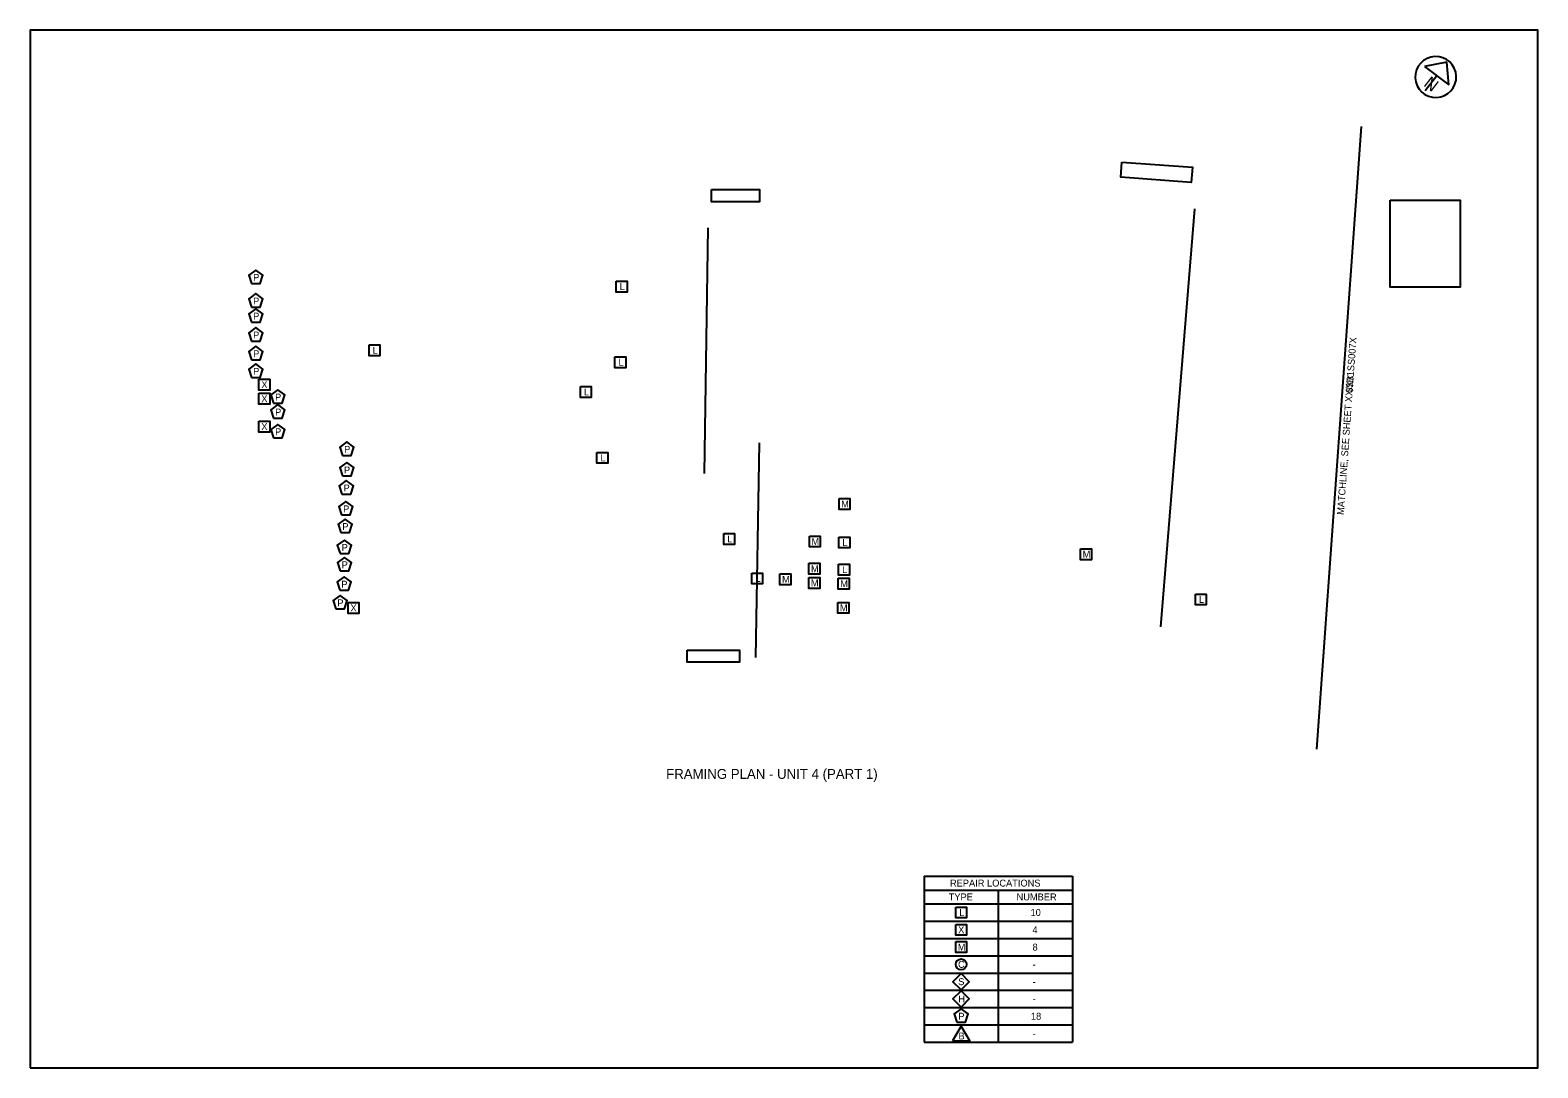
# Model space of a CAD drawing. Extents: x 100 to 130.5, y 100 to 121.
import ezdxf

# ---------------------------------------------------------------- set-up
doc = ezdxf.new("R2010")
doc.units = 0
for name, color, linetype in [('BR_P_Gen_Text', 7, 'Continuous'), ('BR_X_Sub_Centerline', 7, 'Continuous'), ('BR_X_Sub_Text', 7, 'Continuous'), ('SC_Scratch1', 7, 'Continuous'), ('SH_Data', 7, 'Continuous'), ('SH_Masking', 7, 'Continuous')]:
    doc.layers.add(name, color=color, linetype=linetype)

msp = doc.modelspace()

# ---------------------------------------------------------------- linework, layer by layer
at = {"layer": 'BR_P_Gen_Text'}
for p, q in [((126.929, 119.052), (126.022, 106.448)), ((118.083, 103.879), (118.083, 100.519)), ((118.083, 103.879), (121.083, 103.879)), ((121.083, 103.879), (121.083, 100.519)), ((118.083, 103.599), (121.083, 103.599)), ((119.583, 103.599), (119.583, 100.519)), ((118.083, 103.319), (121.083, 103.319)), ((118.083, 102.969), (121.083, 102.969)), ((118.083, 102.619), (121.083, 102.619)), ((118.083, 102.269), (121.083, 102.269)), ((118.083, 101.919), (121.083, 101.919)), ((118.083, 101.569), (121.083, 101.569)), ((118.083, 101.219), (121.083, 101.219)), ((118.083, 100.869), (121.083, 100.869)), ((118.083, 100.519), (121.083, 100.519))]:
    msp.add_line(p, q, dxfattribs=at)
for points in [[(104.479, 115.875), (104.655, 115.875), (104.71, 116.042), (104.567, 116.146), (104.425, 116.042)], [(111.854, 115.92), (112.074, 115.92), (112.074, 115.7), (111.854, 115.7)], [(104.479, 115.396), (104.655, 115.396), (104.71, 115.564), (104.567, 115.668), (104.425, 115.564)], [(104.479, 115.091), (104.655, 115.091), (104.71, 115.259), (104.567, 115.362), (104.425, 115.259)], [(104.479, 114.708), (104.655, 114.708), (104.71, 114.876), (104.567, 114.98), (104.425, 114.876)], [(104.479, 114.33), (104.655, 114.33), (104.71, 114.498), (104.567, 114.602), (104.425, 114.498)], [(106.856, 114.63), (107.076, 114.63), (107.076, 114.41), (106.856, 114.41)], [(111.829, 114.389), (112.049, 114.389), (112.049, 114.169), (111.829, 114.169)], [(104.479, 113.973), (104.655, 113.973), (104.71, 114.141), (104.567, 114.245), (104.425, 114.141)], [(104.627, 113.936), (104.847, 113.936), (104.847, 113.716), (104.627, 113.716)], [(111.13, 113.787), (111.35, 113.787), (111.35, 113.567), (111.13, 113.567)], [(104.627, 113.651), (104.847, 113.651), (104.847, 113.431), (104.627, 113.431)], [(104.923, 113.453), (105.099, 113.453), (105.154, 113.621), (105.011, 113.724), (104.868, 113.621)], [(104.923, 113.15), (105.099, 113.15), (105.154, 113.317), (105.011, 113.421), (104.868, 113.317)], [(104.627, 113.087), (104.847, 113.087), (104.847, 112.867), (104.627, 112.867)], [(104.923, 112.751), (105.099, 112.751), (105.154, 112.918), (105.011, 113.022), (104.868, 112.918)], [(106.319, 112.395), (106.496, 112.395), (106.55, 112.563), (106.407, 112.666), (106.265, 112.563)], [(106.316, 111.978), (106.493, 111.978), (106.547, 112.146), (106.404, 112.249), (106.262, 112.146)], [(111.466, 112.455), (111.686, 112.455), (111.686, 112.235), (111.466, 112.235)], [(106.308, 111.613), (106.484, 111.613), (106.538, 111.781), (106.396, 111.885), (106.253, 111.781)], [(106.299, 111.19), (106.475, 111.19), (106.53, 111.358), (106.387, 111.462), (106.244, 111.358)], [(116.365, 111.52), (116.585, 111.52), (116.585, 111.3), (116.365, 111.3)], [(106.283, 110.832), (106.459, 110.832), (106.514, 111), (106.371, 111.103), (106.229, 111)], [(114.031, 110.813), (114.251, 110.813), (114.251, 110.593), (114.031, 110.593)], [(115.764, 110.762), (115.984, 110.762), (115.984, 110.542), (115.764, 110.542)], [(116.359, 110.742), (116.579, 110.742), (116.579, 110.522), (116.359, 110.522)], [(106.269, 110.409), (106.445, 110.409), (106.499, 110.577), (106.357, 110.68), (106.214, 110.577)], [(121.251, 110.503), (121.471, 110.503), (121.471, 110.283), (121.251, 110.283)], [(106.271, 110.059), (106.448, 110.059), (106.502, 110.227), (106.36, 110.33), (106.217, 110.227)], [(115.754, 110.211), (115.974, 110.211), (115.974, 109.991), (115.754, 109.991)], [(116.353, 110.192), (116.573, 110.192), (116.573, 109.972), (116.353, 109.972)], [(106.263, 109.665), (106.439, 109.665), (106.494, 109.833), (106.351, 109.937), (106.208, 109.833)], [(114.598, 110.014), (114.818, 110.014), (114.818, 109.794), (114.598, 109.794)], [(115.169, 109.996), (115.389, 109.996), (115.389, 109.776), (115.169, 109.776)], [(115.752, 109.924), (115.972, 109.924), (115.972, 109.704), (115.752, 109.704)], [(116.347, 109.908), (116.567, 109.908), (116.567, 109.688), (116.347, 109.688)], [(106.181, 109.289), (106.357, 109.289), (106.412, 109.457), (106.269, 109.56), (106.127, 109.457)], [(123.572, 109.589), (123.792, 109.589), (123.792, 109.369), (123.572, 109.369)], [(106.43, 109.418), (106.65, 109.418), (106.65, 109.198), (106.43, 109.198)], [(116.34, 109.42), (116.56, 109.42), (116.56, 109.2), (116.34, 109.2)], [(118.723, 103.254), (118.943, 103.254), (118.943, 103.034), (118.723, 103.034)], [(118.723, 102.904), (118.943, 102.904), (118.943, 102.684), (118.723, 102.684)], [(118.723, 102.554), (118.943, 102.554), (118.943, 102.334), (118.723, 102.334)], [(118.833, 101.909), (118.998, 101.744), (118.833, 101.579), (118.668, 101.744)], [(118.833, 101.559), (118.998, 101.394), (118.833, 101.229), (118.668, 101.394)], [(118.745, 100.923), (118.922, 100.923), (118.976, 101.091), (118.833, 101.194), (118.691, 101.091)], [(118.66, 100.544), (119.007, 100.544), (118.833, 100.844)]]:
    msp.add_lwpolyline(points, close=True, dxfattribs=at)
msp.add_circle((118.833, 102.094), 0.11, dxfattribs=at)
at = {"layer": 'BR_X_Sub_Centerline'}
for p, q in [((123.554, 117.383), (122.869, 108.926)), ((113.711, 116.998), (113.638, 112.031)), ((114.681, 108.303), (114.755, 112.646))]:
    msp.add_line(p, q, dxfattribs=at)
at = {"layer": 'BR_X_Sub_Text'}
for points in [[(122.087, 118.331), (123.511, 118.226), (123.488, 117.92), (122.065, 118.025)], [(113.781, 117.773), (114.754, 117.773), (114.754, 117.528), (113.781, 117.528)], [(113.291, 108.45), (114.352, 108.45), (114.352, 108.209), (113.291, 108.209)]]:
    msp.add_lwpolyline(points, close=True, dxfattribs=at)
at = {"layer": 'SC_Scratch1'}
msp.add_lwpolyline([(100, 100), (130.5, 100), (130.5, 121), (100, 121)], close=True, dxfattribs=at)
at = {"layer": 'SH_Data'}
for p, q in [((128.662, 120.349), (128.21, 120.265)), ((128.21, 120.265), (128.699, 119.891)), ((128.699, 119.891), (128.662, 120.349)), ((128.454, 120.078), (128.219, 119.771))]:
    msp.add_line(p, q, dxfattribs=at)
msp.add_arc((128.435, 120.052), 0.415, 92.3383, 92.3218, dxfattribs=at)
at = {"layer": 'SH_Masking'}
msp.add_lwpolyline([(127.511, 117.56), (128.927, 117.56), (128.927, 115.801), (127.511, 115.801)], close=True, dxfattribs=at)

# ---------------------------------------------------------------- texts
at = {"layer": 'BR_P_Gen_Text'}
for s, height, p in [('P', 0.14, (104.511, 115.926)), ('L', 0.14, (111.926, 115.74)), ('P', 0.14, (104.511, 115.448)), ('P', 0.14, (104.511, 115.142)), ('P', 0.14, (104.511, 114.76)), ('P', 0.14, (104.511, 114.382)), ('L', 0.14, (106.928, 114.45)), ('P', 0.14, (104.511, 114.025)), ('L', 0.14, (111.901, 114.209)), ('X', 0.14, (104.677, 113.756)), ('X', 0.14, (104.677, 113.471)), ('P', 0.14, (104.955, 113.504)), ('L', 0.14, (111.202, 113.607)), ('P', 0.14, (104.955, 113.201)), ('X', 0.14, (104.677, 112.907)), ('P', 0.14, (104.955, 112.802)), ('P', 0.14, (106.351, 112.446)), ('L', 0.14, (111.538, 112.275)), ('P', 0.14, (106.348, 112.029)), ('P', 0.14, (106.34, 111.665)), ('P', 0.14, (106.331, 111.242)), ('M', 0.14, (116.407, 111.34)), ('P', 0.14, (106.315, 110.883)), ('L', 0.14, (114.103, 110.633)), ('M', 0.14, (115.805, 110.582)), ('P', 0.14, (106.301, 110.46)), ('L', 0.14, (116.431, 110.562)), ('M', 0.14, (121.292, 110.323)), ('P', 0.14, (106.303, 110.11)), ('M', 0.14, (115.796, 110.031)), ('L', 0.14, (116.425, 110.012)), ('P', 0.14, (106.295, 109.717)), ('L', 0.14, (114.67, 109.834)), ('M', 0.14, (115.211, 109.816)), ('M', 0.14, (115.794, 109.744)), ('M', 0.14, (116.388, 109.728)), ('L', 0.14, (123.644, 109.409)), ('P', 0.14, (106.213, 109.34)), ('X', 0.14, (106.48, 109.238)), ('M', 0.14, (116.381, 109.24)), ('FRAMING PLAN - UNIT 4 (PART 1)', 0.2, (112.866, 105.848)), ('REPAIR LOCATIONS', 0.14, (118.608, 103.669)), ('TYPE', 0.14, (118.582, 103.389)), ('NUMBER', 0.14, (119.955, 103.389)), ('L', 0.14, (118.795, 103.074)), ('10', 0.14, (120.237, 103.074)), ('X', 0.14, (118.773, 102.724)), ('4', 0.14, (120.275, 102.724)), ('M', 0.14, (118.765, 102.374)), ('8', 0.14, (120.278, 102.374)), ('C', 0.14, (118.771, 102.024)), ('-', 0.14, (120.28, 102.024)), ('S', 0.14, (118.775, 101.674)), ('-', 0.14, (120.28, 101.674)), ('H', 0.14, (118.777, 101.324)), ('-', 0.14, (120.28, 101.324)), ('P', 0.14, (118.777, 100.974)), ('18', 0.14, (120.245, 100.974)), ('B', 0.14, (118.779, 100.574)), ('-', 0.14, (120.28, 100.624))]:
    msp.add_text(s, height=height, dxfattribs=at).set_placement(p)
for s, p in [('$$B1SS007X', (126.752, 113.658)), ('MATCHLINE, SEE SHEET XX/XX', (126.574, 111.186))]:
    msp.add_text(s, height=0.14, rotation=85.8808, dxfattribs=at).set_placement(p)
at = {"layer": 'SH_Data'}
msp.add_text('N', height=0.25, rotation=322.5585, dxfattribs=at).set_placement((128.175, 119.884))

doc.saveas('drawing.dxf')
